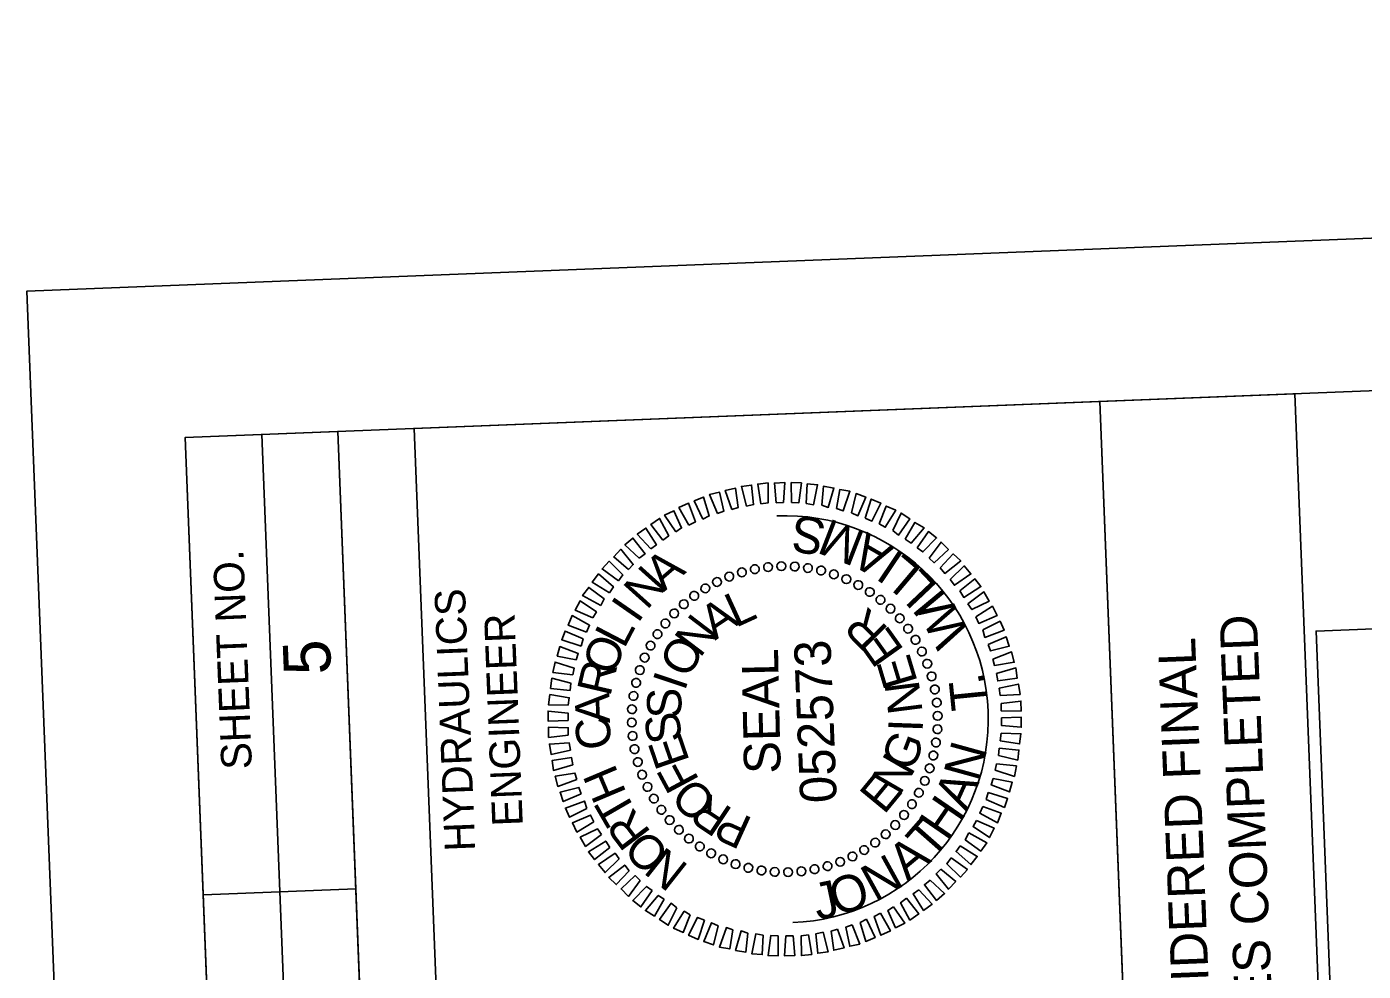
# Model space of a CAD drawing. Extents: x 1627855 to 1629021, y 762567 to 764488.
# Drawn here: x 1627855.1 to 1628074.2, y 764154.6 to 764309.4 of the extents above; entities that cross this region are included whole.
import ezdxf

# ---------------------------------------------------------------- set-up
doc = ezdxf.new("R2010")
doc.units = 0
for name, color, linetype in [('Prop DSN Text', 7, 'Continuous'), ('Scratch_Level_0', 7, 'Continuous'), ('Sheet Clip Boundary CELL', 7, 'Continuous'), ('Sheet Data Field CELL', 7, 'Continuous'), ('Sheet Plan And Profile CELL', 7, 'Continuous'), ('Sheet Plot Border Outside CELL', 7, 'Continuous'), ('Sheet Professional Seal CELL', 7, 'Continuous'), ('Sheet Profile Grid Minor CELL', 7, 'Continuous'), ('Sheet Sticker Exception Certification CELL', 7, 'Continuous')]:
    doc.layers.add(name, color=color, linetype=linetype)

msp = doc.modelspace()

# ---------------------------------------------------------------- linework, layer by layer
at = {"layer": 'Scratch_Level_0'}
msp.add_arc((1627979.36, 764195.89), 33.36, 272.2582, 92.2582, dxfattribs=at)
at = {"layer": 'Sheet Clip Boundary CELL'}
msp.add_lwpolyline([(1628522.47, 764228.52), (1628282.65, 764219.07), (1628066.45, 764210.34), (1628072.87, 764047.54), (1627958.4, 764043.02), (1627966.27, 763843.29), (1627900.75, 763840.71), (1627941.6, 762804.67), (1628337.82, 762820.15), (1628577.63, 762829.61), (1628634.82, 762831.83), (1628637.13, 762773.12), (1628655.42, 762773.84), (1628653.1, 762832.57), (1628984.86, 762845.59), (1628929.69, 764244.53)], close=True, dxfattribs=at)
at = {"layer": 'Sheet Plan And Profile CELL'}
for p, q in [((1627914, 764043.14), (1627906.12, 764243.04)), ((1627901.51, 764042.65), (1627893.63, 764242.54)), ((1627884.09, 764167.11), (1627909.07, 764168.09))]:
    msp.add_line(p, q, dxfattribs=at)
for points in [[(1627881.09, 764242.05), (1627940.19, 762743.21), (1628989.38, 762784.59), (1628930.27, 764283.42)], [(1627922.55, 764143.61), (1627918.61, 764243.53), (1628031.02, 764247.96), (1628034.96, 764148.04)], [(1627888.97, 764042.15), (1627881.09, 764242.05), (1627906.12, 764243.04), (1627914, 764043.14)]]:
    msp.add_lwpolyline(points, close=True, dxfattribs=at)
at = {"layer": 'Sheet Plot Border Outside CELL'}
msp.add_lwpolyline([(1629021.25, 762610.71), (1628954.27, 764309.39), (1627855.12, 764266.04), (1627922.11, 762567.36)], close=True, dxfattribs=at)
at = {"layer": 'Sheet Professional Seal CELL'}
for p, q in [((1627978.82, 764220.98), (1627978.82, 764220.98)), ((1627970.23, 764219.29), (1627970.23, 764219.29)), ((1627972.31, 764219.98), (1627972.31, 764219.98)), ((1627974.49, 764220.46), (1627974.49, 764220.46)), ((1627976.62, 764220.85), (1627976.62, 764220.85)), ((1627981.02, 764220.92), (1627981.02, 764220.92)), ((1627983.19, 764220.66), (1627983.19, 764220.66)), ((1627985.3, 764220.29), (1627985.3, 764220.29)), ((1627987.43, 764219.67), (1627987.43, 764219.67)), ((1627989.46, 764218.85), (1627989.46, 764218.85)), ((1627966.35, 764217.34), (1627966.35, 764217.34)), ((1627968.26, 764218.42), (1627968.26, 764218.42)), ((1627991.45, 764217.93), (1627991.45, 764217.93)), ((1627993.3, 764216.75), (1627993.3, 764216.75)), ((1627962.8, 764214.8), (1627962.8, 764214.8)), ((1627964.5, 764216.12), (1627964.5, 764216.12)), ((1627995.1, 764215.47), (1627995.1, 764215.47)), ((1627961.21, 764213.23), (1627961.21, 764213.23)), ((1627996.71, 764214.03), (1627996.71, 764214.03)), ((1627998.27, 764212.44), (1627998.27, 764212.44)), ((1627959.77, 764211.63), (1627959.77, 764211.63)), ((1627999.59, 764210.74), (1627999.59, 764210.74)), ((1627957.32, 764207.98), (1627957.32, 764207.98)), ((1627958.49, 764209.82), (1627958.49, 764209.82)), ((1628000.81, 764208.89), (1628000.81, 764208.89)), ((1627956.39, 764205.99), (1627956.39, 764205.99)), ((1628001.89, 764206.98), (1628001.89, 764206.98)), ((1627955.57, 764203.95), (1627955.57, 764203.95)), ((1628002.77, 764205.02), (1628002.77, 764205.02)), ((1627954.96, 764201.83), (1627954.96, 764201.83)), ((1628003.45, 764202.94), (1628003.45, 764202.94)), ((1627954.59, 764199.71), (1627954.59, 764199.71)), ((1628003.94, 764200.76), (1628003.94, 764200.76)), ((1627954.32, 764197.55), (1627954.32, 764197.55)), ((1628004.32, 764198.62), (1628004.32, 764198.62)), ((1627954.26, 764195.35), (1627954.26, 764195.35)), ((1627979.36, 764195.89), (1627979.36, 764195.89)), ((1628004.46, 764196.43), (1628004.46, 764196.43)), ((1627954.4, 764193.15), (1627954.4, 764193.15)), ((1628004.39, 764194.22), (1628004.39, 764194.22)), ((1627954.78, 764191.01), (1627954.78, 764191.01)), ((1628004.13, 764192.06), (1628004.13, 764192.06)), ((1627955.27, 764188.83), (1627955.27, 764188.83)), ((1628003.76, 764189.94), (1628003.76, 764189.94)), ((1627955.95, 764186.76), (1627955.95, 764186.76)), ((1628003.15, 764187.82), (1628003.15, 764187.82)), ((1627956.83, 764184.79), (1627956.83, 764184.79)), ((1628001.4, 764183.79), (1628001.4, 764183.79)), ((1628002.33, 764185.78), (1628002.33, 764185.78)), ((1627957.91, 764182.88), (1627957.91, 764182.88)), ((1628000.23, 764181.95), (1628000.23, 764181.95)), ((1627959.13, 764181.03), (1627959.13, 764181.03)), ((1627960.45, 764179.33), (1627960.45, 764179.33)), ((1627998.95, 764180.15), (1627998.95, 764180.15)), ((1627962.01, 764177.74), (1627962.01, 764177.74)), ((1627997.51, 764178.54), (1627997.51, 764178.54)), ((1627963.62, 764176.3), (1627963.62, 764176.3)), ((1627965.42, 764175.02), (1627965.42, 764175.02)), ((1627994.22, 764175.66), (1627994.22, 764175.66)), ((1627995.92, 764176.97), (1627995.92, 764176.97)), ((1627967.27, 764173.84), (1627967.27, 764173.84)), ((1627969.26, 764172.92), (1627969.26, 764172.92)), ((1627990.46, 764173.36), (1627990.46, 764173.36)), ((1627992.37, 764174.43), (1627992.37, 764174.43)), ((1627971.29, 764172.1), (1627971.29, 764172.1)), ((1627973.42, 764171.48), (1627973.42, 764171.48)), ((1627975.53, 764171.12), (1627975.53, 764171.12)), ((1627977.69, 764170.85), (1627977.69, 764170.85)), ((1627979.9, 764170.79), (1627979.9, 764170.79)), ((1627982.1, 764170.92), (1627982.1, 764170.92)), ((1627984.23, 764171.31), (1627984.23, 764171.31)), ((1627986.41, 764171.8), (1627986.41, 764171.8)), ((1627988.49, 764172.48), (1627988.49, 764172.48))]:
    msp.add_line(p, q, dxfattribs=at)
for points in [[(1627973.08, 764230.82), (1627972.25, 764234.04), (1627973.94, 764234.25), (1627974.27, 764231.06)], [(1627975.46, 764231.21), (1627974.94, 764234.44), (1627976.63, 764234.61), (1627976.66, 764231.36)], [(1627977.96, 764231.36), (1627977.68, 764234.6), (1627979.38, 764234.67), (1627979.16, 764231.41)], [(1627980.46, 764231.41), (1627980.43, 764234.66), (1627982.09, 764234.62), (1627981.66, 764231.35)], [(1627982.87, 764231.25), (1627983.04, 764234.46), (1627984.75, 764234.33), (1627984.08, 764231.05)], [(1627965.96, 764228.68), (1627964.54, 764231.68), (1627966.07, 764232.29), (1627966.99, 764229.22)], [(1627968.32, 764229.58), (1627967.05, 764232.73), (1627968.69, 764233.09), (1627969.36, 764229.97)], [(1627970.7, 764230.27), (1627969.62, 764233.38), (1627971.31, 764233.75), (1627971.74, 764230.61)], [(1627985.43, 764230.95), (1627985.71, 764234.07), (1627987.42, 764233.78), (1627986.5, 764230.59)], [(1627987.86, 764230.4), (1627988.38, 764233.52), (1627990.05, 764233.24), (1627988.92, 764230.04)], [(1627990.28, 764229.74), (1627991.06, 764232.88), (1627992.64, 764232.29), (1627991.36, 764229.23)], [(1627992.52, 764228.83), (1627993.55, 764231.97), (1627995.13, 764231.28), (1627993.64, 764228.37)], [(1627961.54, 764226.61), (1627959.68, 764229.34), (1627961.2, 764230.05), (1627962.46, 764227.24)], [(1627963.64, 764227.69), (1627962.03, 764230.58), (1627963.6, 764231.29), (1627964.72, 764228.23)], [(1627994.86, 764227.92), (1627996, 764230.82), (1627997.57, 764230.13), (1627995.83, 764227.36)], [(1627959.39, 764225.22), (1627957.39, 764227.79), (1627958.85, 764228.8), (1627960.36, 764225.96)], [(1627997.06, 764226.81), (1627998.44, 764229.66), (1627999.88, 764228.72), (1627997.99, 764226.04)], [(1627999.11, 764225.39), (1628000.71, 764228.15), (1628002.19, 764227.26), (1628000.09, 764224.77)], [(1627955.5, 764222.27), (1627953.16, 764224.48), (1627954.47, 764225.58), (1627956.47, 764223.01)], [(1627957.39, 764223.84), (1627955.2, 764226.21), (1627956.61, 764227.21), (1627958.32, 764224.48)], [(1628001.07, 764223.96), (1628002.92, 764226.64), (1628004.26, 764225.59), (1628002, 764223.3)], [(1627953.77, 764220.45), (1627951.34, 764222.5), (1627952.49, 764223.75), (1627954.54, 764221.23)], [(1628003.04, 764222.29), (1628004.99, 764224.92), (1628006.18, 764223.71), (1628003.87, 764221.52)], [(1627952.09, 764218.58), (1627949.42, 764220.53), (1627950.57, 764221.77), (1627952.81, 764219.56)], [(1628004.85, 764220.71), (1628006.96, 764222.99), (1628008.21, 764221.84), (1628005.59, 764219.79)], [(1628006.48, 764218.77), (1628008.79, 764221.02), (1628009.89, 764219.71), (1628007.17, 764217.85)], [(1627950.62, 764216.62), (1627947.8, 764218.36), (1627948.85, 764219.7), (1627951.28, 764217.6)], [(1628008.05, 764216.93), (1628010.53, 764218.88), (1628011.53, 764217.62), (1628008.7, 764215.86)], [(1627949.2, 764214.51), (1627946.24, 764216.15), (1627947.23, 764217.49), (1627949.76, 764215.63)], [(1628009.39, 764214.78), (1628012.01, 764216.74), (1628012.87, 764215.22), (1628010.03, 764213.86)], [(1627947.93, 764212.51), (1627945.03, 764213.75), (1627945.82, 764215.28), (1627948.49, 764213.48)], [(1628010.67, 764212.68), (1628013.41, 764214.39), (1628014.17, 764212.87), (1628011.17, 764211.6)], [(1627946.87, 764210.17), (1627943.87, 764211.3), (1627944.51, 764212.88), (1627947.38, 764211.29)], [(1627946.01, 764207.88), (1627942.82, 764208.91), (1627943.36, 764210.33), (1627946.32, 764209.04)], [(1628011.81, 764210.53), (1628014.65, 764211.94), (1628015.31, 764210.46), (1628012.16, 764209.29)], [(1628012.7, 764208.11), (1628015.66, 764209.38), (1628016.17, 764207.85), (1628013.1, 764207.07)], [(1627945.2, 764205.6), (1627942.07, 764206.22), (1627942.51, 764207.79), (1627945.51, 764206.66)], [(1628013.45, 764205.74), (1628016.55, 764206.91), (1628016.97, 764205.22), (1628013.74, 764204.7)], [(1627944.65, 764203.17), (1627941.38, 764203.55), (1627941.71, 764205.26), (1627944.85, 764204.23)], [(1628014.09, 764203.36), (1628017.26, 764204.29), (1628017.47, 764202.64), (1628014.29, 764202.17)], [(1627944.2, 764200.6), (1627940.98, 764200.93), (1627941.17, 764202.59), (1627944.3, 764201.81)], [(1628014.49, 764200.97), (1628017.66, 764201.65), (1628017.93, 764199.96), (1628014.68, 764199.78)], [(1627943.89, 764198.19), (1627940.64, 764198.26), (1627940.87, 764199.92), (1627944.04, 764199.4)], [(1627943.84, 764195.69), (1627940.59, 764195.56), (1627940.58, 764197.21), (1627943.84, 764196.89)], [(1628014.83, 764198.49), (1628018.07, 764198.86), (1628018.09, 764197.21), (1628014.83, 764197.28)], [(1628014.88, 764196.09), (1628018.13, 764196.21), (1628018.14, 764194.56), (1628014.88, 764194.88)], [(1627943.88, 764193.29), (1627940.65, 764192.91), (1627940.63, 764194.56), (1627943.89, 764194.49)], [(1628014.83, 764193.58), (1628018.08, 764193.51), (1628017.85, 764191.85), (1628014.68, 764192.37)], [(1627944.23, 764190.8), (1627941.06, 764190.12), (1627940.79, 764191.81), (1627944.04, 764191.99)], [(1628014.52, 764191.17), (1628017.74, 764190.84), (1628017.55, 764189.19), (1628014.42, 764189.96)], [(1627944.63, 764188.41), (1627941.46, 764187.49), (1627941.25, 764189.13), (1627944.43, 764189.6)], [(1628014.07, 764188.6), (1628017.34, 764188.23), (1628017.01, 764186.51), (1628013.87, 764187.54)], [(1627945.27, 764186.03), (1627942.17, 764184.86), (1627941.75, 764186.55), (1627944.98, 764187.07)], [(1628013.52, 764186.17), (1628016.65, 764185.55), (1628016.21, 764183.98), (1628013.21, 764185.11)], [(1627946.02, 764183.66), (1627943.06, 764182.4), (1627942.55, 764183.93), (1627945.62, 764184.7)], [(1628012.71, 764183.89), (1628015.9, 764182.87), (1628015.36, 764181.44), (1628012.4, 764182.73)], [(1627946.91, 764181.25), (1627944.06, 764179.83), (1627943.41, 764181.31), (1627946.56, 764182.48)], [(1628011.85, 764181.6), (1628014.84, 764180.47), (1628014.21, 764178.9), (1628011.34, 764180.48)], [(1627948.05, 764179.09), (1627945.31, 764177.38), (1627944.55, 764178.9), (1627947.55, 764180.17)], [(1627949.33, 764176.99), (1627946.71, 764175.03), (1627945.85, 764176.55), (1627948.69, 764177.91)], [(1628009.52, 764177.26), (1628012.48, 764175.63), (1628011.49, 764174.28), (1628008.96, 764176.14)], [(1628010.79, 764179.26), (1628013.69, 764178.02), (1628012.9, 764176.49), (1628010.23, 764178.29)], [(1627950.67, 764174.84), (1627948.19, 764172.89), (1627947.19, 764174.15), (1627950.02, 764175.91)], [(1628008.1, 764175.15), (1628010.92, 764173.41), (1628009.87, 764172.07), (1628007.44, 764174.18)], [(1627952.24, 764173), (1627949.93, 764170.76), (1627948.82, 764172.06), (1627951.55, 764173.92)], [(1628006.63, 764173.19), (1628009.3, 764171.25), (1628008.15, 764170), (1628005.91, 764172.21)], [(1627953.87, 764171.06), (1627951.76, 764168.78), (1627950.51, 764169.93), (1627953.13, 764171.98)], [(1628004.95, 764171.32), (1628007.38, 764169.27), (1628006.23, 764168.02), (1628004.18, 764170.54)], [(1627955.68, 764169.48), (1627953.73, 764166.85), (1627952.54, 764168.06), (1627954.85, 764170.25)], [(1627957.65, 764167.81), (1627955.8, 764165.13), (1627954.46, 764166.18), (1627956.72, 764168.47)], [(1628003.22, 764169.51), (1628005.56, 764167.3), (1628004.25, 764166.19), (1628002.25, 764168.77)], [(1627959.61, 764166.38), (1627958.01, 764163.62), (1627956.53, 764164.51), (1627958.63, 764167)], [(1627999.33, 764166.55), (1628001.33, 764163.98), (1627999.87, 764162.97), (1627998.36, 764165.81)], [(1628001.33, 764167.93), (1628003.52, 764165.56), (1628002.11, 764164.56), (1628000.4, 764167.29)], [(1627961.66, 764164.96), (1627960.28, 764162.11), (1627958.84, 764163.05), (1627960.73, 764165.73)], [(1627963.86, 764163.85), (1627962.72, 764160.95), (1627961.15, 764161.64), (1627962.89, 764164.41)], [(1627995.08, 764164.08), (1627996.69, 764161.19), (1627995.12, 764160.48), (1627994, 764163.54)], [(1627997.18, 764165.16), (1627999.04, 764162.44), (1627997.52, 764161.72), (1627996.26, 764164.53)], [(1627966.2, 764162.94), (1627965.17, 764159.8), (1627963.59, 764160.49), (1627965.08, 764163.4)], [(1627968.44, 764162.03), (1627967.66, 764158.9), (1627966.08, 764159.48), (1627967.36, 764162.54)], [(1627990.4, 764162.19), (1627991.67, 764159.04), (1627990.03, 764158.68), (1627989.36, 764161.8)], [(1627992.76, 764163.09), (1627994.18, 764160.09), (1627992.65, 764159.48), (1627991.73, 764162.55)], [(1627970.86, 764161.37), (1627970.34, 764158.25), (1627968.67, 764158.54), (1627969.8, 764161.73)], [(1627973.29, 764160.82), (1627973.01, 764157.71), (1627971.3, 764157.99), (1627972.22, 764161.18)], [(1627975.85, 764160.52), (1627975.68, 764157.31), (1627973.97, 764157.44), (1627974.64, 764160.72)], [(1627978.26, 764160.36), (1627978.29, 764157.11), (1627976.63, 764157.15), (1627977.06, 764160.42)], [(1627980.76, 764160.41), (1627981.04, 764157.17), (1627979.34, 764157.1), (1627979.56, 764160.37)], [(1627983.25, 764160.56), (1627983.78, 764157.33), (1627982.09, 764157.16), (1627982.06, 764160.41)], [(1627985.64, 764160.96), (1627986.47, 764157.74), (1627984.78, 764157.52), (1627984.45, 764160.71)], [(1627988.02, 764161.5), (1627989.09, 764158.39), (1627987.41, 764158.02), (1627986.98, 764161.16)]]:
    msp.add_lwpolyline(points, close=True, dxfattribs=at)
for centre, major_axis in [((1627974.46, 764220.48), (-0.141, 0.706)), ((1627976.63, 764220.82), (-0.078, 0.716)), ((1627978.81, 764220.96), (-0.016, 0.72)), ((1627981, 764220.91), (0.047, 0.718)), ((1627983.17, 764220.67), (0.109, 0.712)), ((1627985.32, 764220.25), (0.171, 0.699)), ((1627968.26, 764218.38), (-0.319, 0.646)), ((1627970.27, 764219.26), (-0.261, 0.671)), ((1627972.34, 764219.96), (-0.202, 0.691)), ((1627987.42, 764219.64), (0.231, 0.682)), ((1627989.46, 764218.84), (0.29, 0.659)), ((1627964.53, 764216.11), (-0.426, 0.581)), ((1627966.35, 764217.33), (-0.374, 0.615)), ((1627991.42, 764217.88), (0.346, 0.631)), ((1627993.29, 764216.74), (0.4, 0.599)), ((1627962.82, 764214.74), (-0.475, 0.541)), ((1627995.06, 764215.45), (0.451, 0.562)), ((1627996.7, 764214.01), (0.498, 0.52)), ((1627959.8, 764211.58), (-0.562, 0.451)), ((1627961.24, 764213.23), (-0.52, 0.498)), ((1627998.21, 764212.42), (0.541, 0.475)), ((1627958.5, 764209.82), (-0.599, 0.4)), ((1627999.58, 764210.72), (0.581, 0.426)), ((1627957.37, 764207.95), (-0.631, 0.346)), ((1628000.8, 764208.9), (0.615, 0.374)), ((1628001.85, 764206.98), (0.646, 0.319)), ((1627956.4, 764205.98), (-0.659, 0.29)), ((1628002.73, 764204.98), (0.671, 0.261)), ((1627955.61, 764203.94), (-0.682, 0.231)), ((1628003.44, 764202.91), (0.691, 0.202)), ((1627955, 764201.84), (-0.699, 0.171)), ((1628003.96, 764200.78), (0.706, 0.141)), ((1627954.57, 764199.7), (-0.712, 0.109)), ((1628004.29, 764198.62), (0.716, 0.078)), ((1627954.33, 764197.52), (-0.718, 0.047)), ((1628004.43, 764196.44), (0.72, 0.016)), ((1627954.29, 764195.34), (-0.72, -0.016)), ((1628004.39, 764194.25), (0.718, -0.047)), ((1627954.43, 764193.15), (-0.716, -0.078)), ((1628004.15, 764192.07), (0.712, -0.109)), ((1627954.76, 764190.99), (-0.706, -0.141)), ((1628003.72, 764189.93), (0.699, -0.171)), ((1627955.28, 764188.86), (-0.691, -0.202)), ((1628003.11, 764187.83), (0.682, -0.231)), ((1627955.99, 764186.79), (-0.671, -0.261)), ((1628002.32, 764185.79), (0.659, -0.29)), ((1627956.87, 764184.79), (-0.646, -0.319)), ((1628001.35, 764183.83), (0.631, -0.346)), ((1627957.92, 764182.87), (-0.615, -0.374)), ((1627959.14, 764181.05), (-0.581, -0.426)), ((1628000.22, 764181.96), (0.599, -0.4)), ((1627960.51, 764179.35), (-0.541, -0.475)), ((1627997.48, 764178.55), (0.52, -0.498)), ((1627998.92, 764180.19), (0.562, -0.451)), ((1627962.02, 764177.77), (-0.498, -0.52)), ((1627963.66, 764176.32), (-0.451, -0.562)), ((1627995.9, 764177.03), (0.475, -0.541)), ((1627965.43, 764175.03), (-0.4, -0.599)), ((1627992.37, 764174.45), (0.374, -0.615)), ((1627994.19, 764175.66), (0.426, -0.581)), ((1627967.3, 764173.9), (-0.346, -0.631)), ((1627969.26, 764172.93), (-0.29, -0.659)), ((1627971.3, 764172.14), (-0.231, -0.682)), ((1627988.45, 764172.51), (0.261, -0.671)), ((1627990.46, 764173.39), (0.319, -0.646)), ((1627973.4, 764171.52), (-0.171, -0.699)), ((1627975.55, 764171.1), (-0.109, -0.712)), ((1627977.72, 764170.86), (-0.047, -0.718)), ((1627979.91, 764170.81), (0.016, -0.72)), ((1627982.09, 764170.96), (0.078, -0.716)), ((1627984.26, 764171.29), (0.141, -0.706)), ((1627986.38, 764171.81), (0.202, -0.691))]:
    msp.add_ellipse(centre, major_axis=major_axis, ratio=0.999708, dxfattribs=at)
at = {"layer": 'Sheet Sticker Exception Certification CELL'}
for p, q in [((1628038.89, 764048.07), (1628031.01, 764247.96)), ((1628031.02, 764247.96), (1628062.98, 764249.22)), ((1628062.96, 764249.22), (1628070.84, 764049.33))]:
    msp.add_line(p, q, dxfattribs=at)

# ---------------------------------------------------------------- texts
at = {"layer": 'Prop DSN Text'}
for s, rotation, p in [('S', 170.5234, (1627986.38, 764228.54)), ('M', 158.8769, (1627992.83, 764226.45)), ('A', 149.947, (1627997.41, 764223.99)), ('I', 146.1065, (1627999.25, 764222.72)), ('L', 139.7681, (1628002.09, 764220.36)), ('L', 133.4297, (1628004.65, 764217.7)), ('I', 129.5892, (1628006.06, 764215.96)), ('W', 116.928, (1628009.81, 764209.62)), ('T', 95.6803, (1628012.71, 764197.65)), ('.', 102.5495, (1628012.26, 764201.63)), ('N', 74.5419, (1628011.1, 764185.5)), ('A', 65.6119, (1628009.11, 764180.7)), ('H', 55.5267, (1628005.99, 764175.73)), ('T', 48.6575, (1628003.39, 764172.69)), ('A', 39.7275, (1627999.49, 764169.24)), ('N', 28.8929, (1627994.13, 764165.93)), ('J', 11.9042, (1627984.73, 764162.92)), ('O', 17.2153, (1627987.76, 764163.56))]:
    msp.add_text(s, height=6, rotation=rotation, dxfattribs=at).set_placement(p)
at = {"layer": 'Sheet Data Field CELL'}
msp.add_text('5', height=7.75, rotation=92.2582, dxfattribs=at).set_placement((1627905.03, 764203.3))
at = {"layer": 'Sheet Plan And Profile CELL'}
for s, p in [('SHEET NO.', (1627892.04, 764187.74)), ('HYDRAULICS', (1627928.64, 764174.32)), ('ENGINEER', (1627936.44, 764178.43))]:
    msp.add_text(s, height=5, rotation=92.2582, dxfattribs=at).set_placement(p)
at = {"layer": 'Sheet Professional Seal CELL'}
for s, height, rotation, p in [('N', 5.64, 48.0771, (1627956.74, 764213.66)), ('A', 5.64, 40.8753, (1627959.57, 764216.72)), ('I', 5.64, 55.2783, (1627955.28, 764211.45)), ('A', 5.64, 34.0185, (1627967.94, 764208.75)), ('L', 5.64, 24.659, (1627971.31, 764210.83)), ('N', 5.64, 52.7348, (1627965.46, 764205.8)), ('R', 5.64, 134.7396, (1627996.54, 764210.67)), ('L', 5.64, 62.4791, (1627953.04, 764207.31)), ('E', 5.64, 125.3823, (1627999.03, 764207.22)), ('O', 5.64, 69.6794, (1627951.36, 764202.84)), ('O', 5.64, 62.0917, (1627963.59, 764202.37)), ('SEAL', 5.998, 91.2582, (1627978.71, 764187)), ('E', 5.64, 106.67, (1628001.19, 764202)), ('R', 5.64, 76.8793, (1627950.75, 764199.46)), ('I', 5.64, 71.4478, (1627962.97, 764200.34)), ('N', 5.64, 97.3146, (1628001.98, 764197.08)), ('A', 5.64, 91.2785, (1627950.71, 764195.26)), ('S', 5.64, 90.1586, (1627962.44, 764196.02)), ('S', 5.64, 99.5138, (1627962.63, 764192.42)), ('C', 5.64, 98.4781, (1627951.17, 764191.32)), ('I', 5.64, 87.9594, (1628001.96, 764193.72)), ('E', 5.64, 108.8693, (1627963.82, 764189.02)), ('G', 5.64, 69.2484, (1628000.32, 764187.1)), ('H', 5.64, 112.8777, (1627953.47, 764183.81)), ('F', 5.64, 118.2252, (1627965.44, 764185.88)), ('N', 5.64, 59.8921, (1627998.22, 764183.22)), ('E', 5.64, 50.5351, (1627995.64, 764180.12)), ('O', 5.64, 136.9394, (1627968.52, 764182.7)), ('R', 5.64, 146.2978, (1627971.04, 764181.05)), ('T', 5.64, 120.078, (1627955.24, 764180.62)), ('R', 5.64, 127.2787, (1627957.57, 764177.31)), ('P', 5.64, 155.6571, (1627974.3, 764179.57)), ('O', 5.64, 134.4799, (1627960.81, 764173.99)), ('N', 5.64, 141.6817, (1627963.8, 764171.8))]:
    msp.add_text(s, height=height, rotation=rotation, dxfattribs=at).set_placement(p)
at = {"layer": 'Sheet Profile Grid Minor CELL'}
msp.add_text('052573', height=5.998, rotation=92.2582, dxfattribs=at).set_placement((1627987.91, 764182.26))
at = {"layer": 'Sheet Sticker Exception Certification CELL'}
for s, p in [('UNLESS ALL SIGNATURES COMPLETED', (1628062.98, 764054.91)), ('DOCUMENT NOT CONSIDERED FINAL', (1628052.5, 764060.24))]:
    msp.add_text(s, height=6.124, rotation=92.2582, dxfattribs=at).set_placement(p)

doc.saveas('drawing.dxf')
